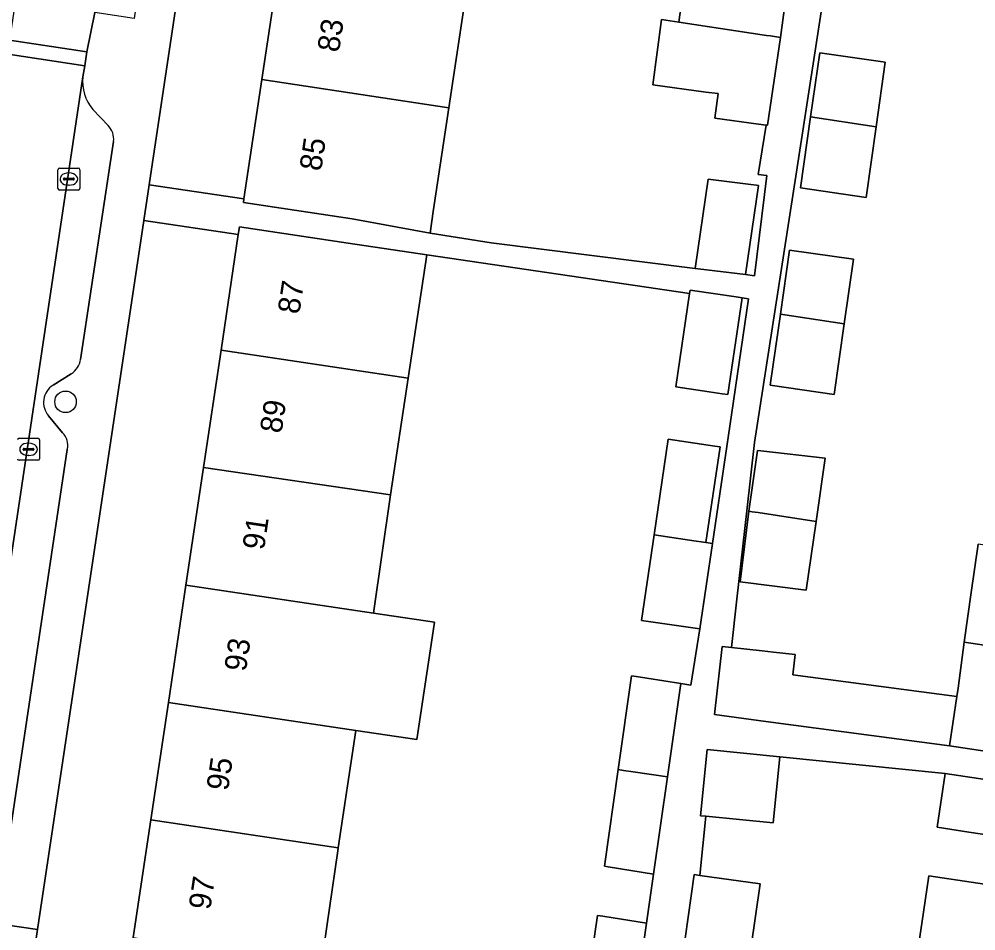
# Model space of a CAD drawing. Extents: x 163008 to 163854, y 382777 to 383982.
# Drawn here: x 163559.84 to 163603.32, y 383304.24 to 383345.69 of the extents above; entities that cross this region are included whole.
import ezdxf

# ---------------------------------------------------------------- set-up
doc = ezdxf.new("R2010")
doc.units = 0
for name, color, linetype in [('IMGEO_Boom', 7, 'Continuous'), ('IMGEO_Erf', 7, 'Continuous'), ('IMGEO_Kolk', 7, 'Continuous'), ('IMGEO_Pand', 7, 'Continuous'), ('IMGEO_Pand_nummerreeks', 7, 'Continuous'), ('IMGEO_Parkeervlak_open', 7, 'Continuous'), ('IMGEO_Rijbaan_lokaal_open', 7, 'Continuous'), ('IMGEO_Voetpad_gesloten', 7, 'Continuous'), ('IMGEO_Voetpad_open', 7, 'Continuous')]:
    doc.layers.add(name, color=color, linetype=linetype)

msp = doc.modelspace()

# ---------------------------------------------------------------- linework, layer by layer
at = {"layer": 'IMGEO_Boom'}
msp.add_circle((163561.947, 383328.293), 0.489, dxfattribs=at)
at = {"layer": 'IMGEO_Erf'}
for points in [[(163574.081, 383364.302), (163574.883, 383369.642), (163575.685, 383374.982), (163576.525, 383380.571), (163572.205, 383381.228), (163565.745, 383338.165), (163570.056, 383337.518), (163570.871, 383342.941), (163571.674, 383348.281), (163572.476, 383353.621), (163573.278, 383358.962)], [(163598.781, 383340.797), (163598.324, 383337.589), (163595.342, 383338.015), (163595.804, 383341.244), (163596.22, 383344.157), (163599.2, 383343.731)], [(163567.416, 383319.964), (163568.214, 383325.305), (163569.013, 383330.646), (163569.798, 383335.9), (163565.502, 383336.544), (163560.664, 383304.297), (163559.867, 383298.985), (163564.184, 383298.337), (163565.022, 383303.942), (163565.82, 383309.283), (163566.618, 383314.624)], [(163597.334, 383331.839), (163596.876, 383328.63), (163593.974, 383329.045), (163594.436, 383332.274), (163594.852, 383335.187), (163597.753, 383334.772)], [(163596.463, 383325.733), (163596.053, 383322.858), (163595.607, 383319.734), (163592.605, 383320.103), (163592.992, 383323.316), (163593.388, 383326.078), (163593.547, 383326.06)]]:
    msp.add_lwpolyline(points, close=True, dxfattribs=at)
for points in [[(163610.875, 383371.224), (163600.422, 383372.817), (163597.987, 383357.048), (163595.131, 383338.555), (163593.257, 383326.439), (163592.908, 383323.329), (163592.458, 383319.316), (163592.215, 383317.122), (163593.606, 383316.968), (163594.126, 383316.91), (163595.099, 383316.802), (163594.998, 383315.886), (163602.45, 383314.891), (163602.508, 383315.275), (163602.792, 383317.366), (163603.099, 383319.625), (163603.427, 383321.819)], [(163580.167, 383347.004), (163579.364, 383341.664), (163578.655, 383336.945), (163578.524, 383335.954), (163581.296, 383335.517), (163590.556, 383334.358), (163591.153, 383338.411), (163591.636, 383338.351), (163593.092, 383338.171), (163593.347, 383338.139), (163593.442, 383338.128), (163592.845, 383334.075), (163593.251, 383334.025), (163593.814, 383338.584), (163593.422, 383338.633), (163593.789, 383340.873), (163593.443, 383340.919), (163591.461, 383341.185), (163591.611, 383342.304), (163591.049, 383342.379), (163588.634, 383342.704), (163589.033, 383345.671), (163589.819, 383345.553), (163589.879, 383346)], [(163585.533, 383300.878), (163586.115, 383304.943), (163586.359, 383304.905), (163588.35, 383304.587), (163588.669, 383306.82), (163586.607, 383307.149), (163586.435, 383307.177), (163587.063, 383311.569), (163587.674, 383315.84), (163587.987, 383315.79), (163588.37, 383315.729), (163589.909, 383315.483), (163590.369, 383315.41), (163590.777, 383317.965), (163588.117, 383318.357), (163588.69, 383322.245), (163589.332, 383326.596), (163591.454, 383326.283), (163591.692, 383326.248), (163591.05, 383321.893), (163591.349, 383321.848), (163592.137, 383327.191), (163592.99, 383332.977), (163592.69, 383333.021), (163592.042, 383328.625), (163591.794, 383328.661), (163591.193, 383328.75), (163589.682, 383328.973), (163590.308, 383333.217), (163578.361, 383334.978), (163577.519, 383329.375), (163576.721, 383324.06), (163575.937, 383318.691), (163578.714, 383318.276), (163578.697, 383318.166), (163577.912, 383312.937), (163575.14, 383313.351), (163574.338, 383308.01), (163574.317, 383307.87), (163573.568, 383302.665)], [(163600.516, 383302.251), (163600.863, 383304.571), (163601.187, 383306.734), (163605.638, 383306.068), (163605.97, 383308.288), (163602.995, 383308.733), (163601.563, 383308.947), (163601.929, 383311.395), (163594.409, 383312.154), (163594.108, 383309.145), (163591.043, 383309.451), (163590.774, 383306.762), (163593.512, 383306.37), (163593.092, 383303.437)]]:
    msp.add_lwpolyline(points, dxfattribs=at)
at = {"layer": 'IMGEO_Kolk'}
for p, q in [((163561.671, 383338.922), (163562.523, 383338.922)), ((163561.596, 383337.996), (163561.596, 383338.848)), ((163562.084, 383338.702), (163562.109, 383338.702)), ((163562.597, 383338.848), (163562.597, 383337.996)), ((163561.855, 383338.416), (163561.855, 383338.428)), ((163562.293, 383338.379), (163561.895, 383338.379)), ((163561.898, 383338.465), (163562.296, 383338.465)), ((163562.107, 383338.142), (163562.082, 383338.142)), ((163562.339, 383338.428), (163562.339, 383338.416)), ((163562.523, 383337.922), (163561.671, 383337.922)), ((163559.837, 383326.633), (163560.689, 383326.633)), ((163560.25, 383326.413), (163560.275, 383326.413)), ((163560.763, 383326.559), (163560.763, 383325.707)), ((163560.021, 383326.127), (163560.021, 383326.139)), ((163560.459, 383326.09), (163560.061, 383326.09)), ((163560.064, 383326.176), (163560.462, 383326.176)), ((163560.505, 383326.139), (163560.505, 383326.127)), ((163560.689, 383325.633), (163559.837, 383325.633)), ((163560.273, 383325.853), (163560.248, 383325.853))]:
    msp.add_line(p, q, dxfattribs=at)
for points in [[(163561.671, 383338.922), (163562.523, 383338.922)], [(163561.596, 383337.996), (163561.596, 383338.848)], [(163562.597, 383338.848), (163562.597, 383337.996)], [(163562.523, 383337.922), (163561.671, 383337.922)], [(163559.837, 383326.633), (163560.689, 383326.633)], [(163560.763, 383326.559), (163560.763, 383325.707)], [(163560.689, 383325.633), (163559.837, 383325.633)]]:
    msp.add_lwpolyline(points, dxfattribs=at)
for centre, radius, start, end in [((163561.673, 383338.846), 0.0765, 91.552, 178.448), ((163561.673, 383338.846), 0.0765, 91.552, 178.448), ((163562.521, 383338.846), 0.0765, 1.552, 88.448), ((163562.521, 383338.846), 0.0765, 1.552, 88.448), ((163561.895, 383338.425), 0.0403, 85.8775, 175.7526), ((163561.892, 383338.415), 0.0366, 178.938, 274.7102), ((163562.296, 383338.422), 0.043, 264.8664, 352.4533), ((163562.3, 383338.427), 0.0386, 1.7309, 96.639), ((163561.673, 383337.998), 0.0765, 181.552, 268.448), ((163561.673, 383337.998), 0.0765, 181.552, 268.448), ((163562.521, 383337.998), 0.0765, 271.552, 358.448), ((163562.521, 383337.998), 0.0765, 271.552, 358.448), ((163559.839, 383326.557), 0.0765, 91.552, 178.448), ((163559.839, 383326.557), 0.0765, 91.552, 178.448), ((163560.687, 383326.557), 0.0765, 1.552, 88.448), ((163560.687, 383326.557), 0.0765, 1.552, 88.448), ((163560.061, 383326.136), 0.0403, 85.8775, 175.7526), ((163560.058, 383326.126), 0.0366, 178.938, 274.7102), ((163560.462, 383326.133), 0.043, 264.8664, 352.4533), ((163560.466, 383326.138), 0.0386, 1.7309, 96.639), ((163559.839, 383325.709), 0.0765, 181.552, 268.448), ((163559.839, 383325.709), 0.0765, 181.552, 268.448), ((163560.687, 383325.709), 0.0765, 271.552, 358.448), ((163560.687, 383325.709), 0.0765, 271.552, 358.448)]:
    msp.add_arc(centre, radius, start, end, dxfattribs=at)
for centre, major_axis, ratio, start_param, end_param in [((163562.083, 383338.422), (-0.387, 0.002), 0.722429, 4.712389, 7.853982), ((163562.108, 383338.422), (-0.39, 0.002), 0.717154, 1.570796, 4.712389), ((163560.249, 383326.133), (-0.387, 0.002), 0.722429, 4.712389, 7.853982), ((163560.274, 383326.133), (-0.39, 0.002), 0.717154, 1.570796, 4.712389)]:
    msp.add_ellipse(centre, major_axis=major_axis, ratio=ratio, start_param=start_param, end_param=end_param, dxfattribs=at)
at = {"layer": 'IMGEO_Pand'}
for points in [[(163594.982, 383348.932), (163591.919, 383349.343), (163590.356, 383349.553), (163589.879, 383346), (163589.819, 383345.553), (163593.795, 383344.955), (163593.982, 383344.927), (163594.435, 383344.859)], [(163579.364, 383341.664), (163580.167, 383347.004), (163571.674, 383348.281), (163570.871, 383342.941)], [(163594.435, 383344.859), (163593.982, 383344.927), (163593.795, 383344.955), (163589.819, 383345.553), (163589.033, 383345.671), (163588.634, 383342.704), (163591.049, 383342.379), (163591.611, 383342.304), (163591.461, 383341.185), (163593.443, 383340.919), (163593.789, 383340.873), (163593.846, 383340.865)], [(163596.22, 383344.157), (163595.804, 383341.244), (163598.781, 383340.797), (163599.2, 383343.731)], [(163579.364, 383341.664), (163570.871, 383342.941), (163570.056, 383337.518), (163570.032, 383337.355), (163574.976, 383336.612), (163578.524, 383335.954), (163578.655, 383336.945)], [(163598.781, 383340.797), (163595.804, 383341.244), (163595.342, 383338.015), (163598.324, 383337.589)], [(163590.556, 383334.358), (163590.697, 383334.34), (163592.845, 383334.075), (163593.442, 383338.128), (163593.347, 383338.139), (163593.092, 383338.171), (163591.636, 383338.351), (163591.153, 383338.411)], [(163578.361, 383334.978), (163574.796, 383335.513), (163569.851, 383336.256), (163569.798, 383335.9), (163569.013, 383330.646), (163577.519, 383329.375)], [(163594.436, 383332.274), (163597.334, 383331.839), (163597.753, 383334.772), (163594.852, 383335.187)], [(163592.69, 383333.021), (163592.423, 383333.06), (163590.33, 383333.369), (163590.308, 383333.217), (163589.682, 383328.973), (163591.193, 383328.75), (163591.794, 383328.661), (163592.042, 383328.625)], [(163597.334, 383331.839), (163594.436, 383332.274), (163593.974, 383329.045), (163596.876, 383328.63)], [(163577.519, 383329.375), (163569.013, 383330.646), (163568.214, 383325.305), (163576.721, 383324.06)], [(163588.69, 383322.245), (163590.613, 383321.958), (163590.83, 383321.926), (163591.05, 383321.893), (163591.692, 383326.248), (163591.454, 383326.283), (163589.332, 383326.596)], [(163592.992, 383323.316), (163593.151, 383323.293), (163593.418, 383323.253), (163596.053, 383322.858), (163596.463, 383325.733), (163593.547, 383326.06), (163593.388, 383326.078)], [(163576.721, 383324.06), (163568.214, 383325.305), (163567.416, 383319.964), (163575.937, 383318.691)], [(163596.053, 383322.858), (163593.418, 383323.253), (163593.151, 383323.293), (163592.992, 383323.316), (163592.605, 383320.103), (163595.607, 383319.734)], [(163591.349, 383321.848), (163591.05, 383321.893), (163590.83, 383321.926), (163590.613, 383321.958), (163588.69, 383322.245), (163588.117, 383318.357), (163590.777, 383317.965)], [(163615.691, 383319.982), (163603.427, 383321.819), (163603.099, 383319.625), (163602.792, 383317.366), (163607.218, 383316.703), (163615.026, 383315.533)], [(163578.697, 383318.166), (163578.714, 383318.276), (163575.937, 383318.691), (163567.416, 383319.964), (163566.618, 383314.624), (163575.14, 383313.351), (163577.912, 383312.937)], [(163615.026, 383315.533), (163607.218, 383316.703), (163602.792, 383317.366), (163602.508, 383315.275), (163602.45, 383314.891), (163602.115, 383312.652), (163609.378, 383311.566), (163614.322, 383310.826)], [(163593.606, 383316.968), (163592.215, 383317.122), (163591.787, 383317.169), (163591.446, 383314.075), (163593.778, 383313.764), (163602.115, 383312.652), (163602.45, 383314.891), (163594.998, 383315.886), (163595.099, 383316.802), (163594.126, 383316.91)], [(163589.909, 383315.483), (163588.37, 383315.729), (163587.987, 383315.79), (163587.674, 383315.84), (163587.063, 383311.569), (163587.307, 383311.533), (163587.746, 383311.468), (163589.301, 383311.236)], [(163565.82, 383309.283), (163574.338, 383308.01), (163575.14, 383313.351), (163566.618, 383314.624)], [(163594.409, 383312.154), (163591.109, 383312.484), (163590.808, 383309.474), (163591.043, 383309.451), (163594.108, 383309.145)], [(163589.301, 383311.236), (163587.746, 383311.468), (163587.307, 383311.533), (163587.063, 383311.569), (163586.435, 383307.177), (163586.607, 383307.149), (163588.669, 383306.82)], [(163614.133, 383309.568), (163609.189, 383310.308), (163601.929, 383311.395), (163601.563, 383308.947), (163602.995, 383308.733), (163605.97, 383308.288), (163605.638, 383306.068), (163613.435, 383304.901)], [(163574.317, 383307.87), (163574.338, 383308.01), (163565.82, 383309.283), (163565.022, 383303.942), (163573.568, 383302.665)], [(163593.512, 383306.37), (163590.774, 383306.762), (163590.52, 383306.798), (163590.104, 383303.885), (163593.092, 383303.437)], [(163613.435, 383304.901), (163605.638, 383306.068), (163601.187, 383306.734), (163600.863, 383304.571), (163600.516, 383302.251), (163612.765, 383300.418)], [(163588.35, 383304.587), (163586.359, 383304.905), (163586.115, 383304.943), (163585.533, 383300.878), (163585.711, 383300.851), (163585.959, 383300.814), (163587.771, 383300.543)]]:
    msp.add_lwpolyline(points, close=True, dxfattribs=at)
at = {"layer": 'IMGEO_Parkeervlak_open'}
for points in [[(163562.734, 383343.07), (163557.024, 383304.899), (163558.474, 383304.626)], [(163563.879, 383340.85), (163563.181, 383341.586)], [(163562.631, 383330.216), (163564.127, 383340.129)], [(163561.38, 383329.047), (163562.208, 383329.569)], [(163561.809, 383326.877), (163561.175, 383327.656)], [(163558.893, 383305.294), (163562.025, 383326.132)]]:
    msp.add_lwpolyline(points, dxfattribs=at)
for centre, radius, start, end in [((163564.65, 383342.838), 1.93, 173.0842, 220.4418), ((163563.309, 383340.251), 0.827, 351.5243, 46.4387), ((163561.651, 383330.395), 0.996, 303.982, 349.6658), ((163561.869, 383328.264), 0.923, 121.9958, 221.2368), ((163561.288, 383326.322), 0.761, 345.5469, 46.7904)]:
    msp.add_arc(centre, radius, start, end, dxfattribs=at)
at = {"layer": 'IMGEO_Rijbaan_lokaal_open'}
for points in [[(163559.339, 383344.103), (163562.816, 383343.571), (163562.919, 383344.203), (163559.406, 383344.741)], [(163562.734, 383343.07), (163562.816, 383343.571), (163559.339, 383344.103), (163559.289, 383343.624), (163553.5, 383305.433), (163557.024, 383304.899)]]:
    msp.add_lwpolyline(points, close=True, dxfattribs=at)
at = {"layer": 'IMGEO_Voetpad_gesloten'}
msp.add_lwpolyline([(163561.372, 383357.894), (163559.406, 383344.741), (163562.919, 383344.203), (163563.28, 383346.001), (163563.93, 383350.466), (163564.063, 383351.377), (163564.714, 383355.85), (163564.873, 383357.345)], close=True, dxfattribs=at)
at = {"layer": 'IMGEO_Voetpad_open'}
for points in [[(163558.474, 383304.626), (163560.664, 383304.297), (163565.502, 383336.544), (163565.745, 383338.165), (163572.205, 383381.228)], [(163609.378, 383311.566), (163602.115, 383312.652), (163593.778, 383313.764), (163591.446, 383314.075), (163591.787, 383317.169), (163592.215, 383317.122), (163592.458, 383319.316), (163592.908, 383323.329), (163593.257, 383326.439), (163595.131, 383338.555), (163597.987, 383357.048), (163600.422, 383372.817), (163610.875, 383371.224)], [(163565.038, 383358.436), (163564.969, 383357.978), (163564.873, 383357.345), (163564.714, 383355.85), (163566.516, 383355.588), (163565.865, 383351.115), (163564.063, 383351.377), (163563.93, 383350.466), (163565.712, 383350.189), (163565.059, 383345.715), (163563.28, 383346.001), (163562.919, 383344.203), (163562.816, 383343.571), (163562.734, 383343.07)], [(163594.982, 383348.932), (163594.435, 383344.859), (163593.846, 383340.865), (163593.789, 383340.873), (163593.422, 383338.633), (163593.814, 383338.584), (163593.251, 383334.025), (163592.845, 383334.075), (163590.697, 383334.34), (163590.556, 383334.358), (163581.296, 383335.517), (163578.524, 383335.954), (163574.976, 383336.612), (163570.032, 383337.355), (163570.056, 383337.518), (163565.745, 383338.165), (163565.502, 383336.544), (163569.798, 383335.9), (163569.851, 383336.256), (163574.796, 383335.513), (163578.361, 383334.978), (163590.308, 383333.217), (163590.33, 383333.369), (163592.423, 383333.06), (163592.69, 383333.021), (163592.99, 383332.977), (163592.137, 383327.191), (163591.349, 383321.848), (163590.777, 383317.965), (163590.369, 383315.41), (163589.909, 383315.483), (163589.301, 383311.236), (163588.669, 383306.82), (163588.35, 383304.587), (163587.771, 383300.543)], [(163563.181, 383341.586), (163563.879, 383340.85)], [(163564.127, 383340.129), (163562.631, 383330.216)], [(163562.208, 383329.569), (163561.38, 383329.047)], [(163561.175, 383327.656), (163561.809, 383326.877)], [(163562.025, 383326.132), (163558.893, 383305.294)], [(163590.104, 383303.885), (163590.52, 383306.798), (163590.774, 383306.762), (163591.043, 383309.451), (163590.808, 383309.474), (163591.109, 383312.484), (163594.409, 383312.154), (163601.929, 383311.395), (163609.189, 383310.308)], [(163559.698, 383297.858), (163559.867, 383298.985), (163560.664, 383304.297), (163558.474, 383304.626), (163557.63, 383304.071)]]:
    msp.add_lwpolyline(points, dxfattribs=at)
for centre, radius, start, end in [((163564.65, 383342.838), 1.93, 173.0842, 220.4418), ((163563.309, 383340.251), 0.827, 351.5243, 46.4387), ((163561.651, 383330.395), 0.996, 303.982, 349.6658), ((163561.869, 383328.264), 0.923, 121.9958, 221.2368), ((163561.288, 383326.322), 0.761, 345.5469, 46.7904)]:
    msp.add_arc(centre, radius, start, end, dxfattribs=at)

# ---------------------------------------------------------------- texts
at = {"layer": 'IMGEO_Pand_nummerreeks'}
for s, rotation, p in [('83', 81.4555, (163574.37, 383344.153)), ('85', 81.4574, (163573.559, 383338.751)), ('87', 81.4975, (163572.568, 383332.246)), ('89', 81.4975, (163571.759, 383326.829)), ('91', 81.4975, (163570.965, 383321.523)), ('93', 81.4975, (163570.14, 383315.995)), ('95', 81.5, (163569.33, 383310.578)), ('97', 81.4975, (163568.521, 383305.161))]:
    msp.add_text(s, height=1, rotation=rotation, dxfattribs=at).set_placement(p)

doc.saveas('drawing.dxf')
